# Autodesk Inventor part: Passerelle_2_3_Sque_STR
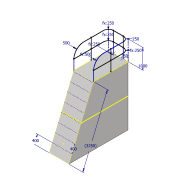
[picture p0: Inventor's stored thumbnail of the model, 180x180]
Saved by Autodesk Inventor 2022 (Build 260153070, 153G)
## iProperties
Created: 2018-07
Part Number: Passerelle_2_3_Sque_STR
Material: Générique
Document SubType Name: Modeling
Designer: Fabian Perrée
Appearance: Par défaut
Surface Area: 252500 cm^2
Volume: 7.125e+06 cm^3
Author: Fabian Perrée
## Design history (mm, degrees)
sketch "Esquisse1"
  geometry: L1 (-500, 0)-(500, 0); L2 (500, 0)-(500, 3000); L3 (500, 3000)-(-500, 3000); L4 (-500, 3000)-(-500, 0); 2 further points
  constraints: 8 end point, 2 parallel, 1 coincident, 1 horizontal, 1 midpoint, 1 perpendicular
  dimensions: "d0" = 3000 distance of L3.end L1.start; "d1" = 1000 distance of L2.end L3.end
extrude "Extrusion1" new body sketch "Esquisse1" stored distance "d2" = 3000; taper "d3" = 0 deg
sketch "Esquisse2"
  geometry: L1 (3000, 3000)-(0, 3000) reference; L2 (3000, 0)-(0, 0) reference; L3 (3000, 3000)-(1250, 3000); L4 (1250, 3000)-(0, 0); L5 (1250, 3000)-(0, 3000); L6 (0, 3000)-(0, 0); 1 further point
  constraints: 8 end point, 1 collinear, 1 perpendicular, 1 point on line
  dimensions: "d4" = 1750 distance of L1.start L3.end
extrude "Extrusion2" cut sketch "Esquisse2" extent not by distance; stored distance "d5" = 3000; taper "d6" = 0 deg
sketch "Esquisse3" dims "d14" = 10
  geometry: L1 (0, 0)-(0, 3250) reference; L2 (0, 0)-(1000, 0) reference; L3 (1000, 3250)-(1000, 0) reference; L4 (0, 3250)-(1000, 3250) reference; L5 (1000, 1153.846)-(1000, 0) reference; L6 (1000, 400)-(0, 400); L7 (0, 0)-(0, 1153.846) reference; L8 (1000, 800)-(0, 800); L9 (1000, 1200)-(0, 1200); L10 (1000, 1600)-(0, 1600); L11 (1000, 2000)-(0, 2000); L12 (1000, 2400)-(0, 2400); L13 (1000, 2800)-(0, 2800); L14 (1000, 3200)-(0, 3200); 1 further point
  constraints: 16 end point, 2 point on line, 1 perpendicular, 1 vertical, 21 other
  dimensions: "d7" = 400 distance between parallel lines of L2 L6; "d8" = 3250 distance of L3.start L2.end (derived); "d11" = 400 distance of L6.start L8.start
node "Plan de construction1"
sketch "Esquisse4"
  geometry: L1 (1000, 400)-(0, 400) reference; L2 (1000, 800)-(0, 800) reference; L3 (1000, 1200)-(0, 1200) reference; L4 (1000, 1600)-(0, 1600) reference; L5 (1000, 2000)-(0, 2000) reference; L6 (1000, 2400)-(0, 2400) reference; L7 (1000, 2800)-(0, 2800) reference; L8 (1000, 3200)-(0, 3200) reference; 1 further point
node "Plan de construction2"
sketch "Esquisse5"
  geometry: L1 (1000, -2375)-(0, -2375) reference; L2 (0, -2375)-(0, 0) reference; L3 (0, 0)-(1000, 0) reference; L4 (1000, 0)-(1000, -2375) reference; 1 further point
  node "Projeter les arêtes coupées1"
sketch "Esquisse 3D1" dims "d17" = 1000, "d18" = 500, "d19" = 500 (= d18), "d20" = 250, "d21" = 250 (= d20), "d22" = 250 (= d20), "d23" = 250 (= d20), "d26" = 250, "d27" = 250 (= d26)
node "Solide1"
